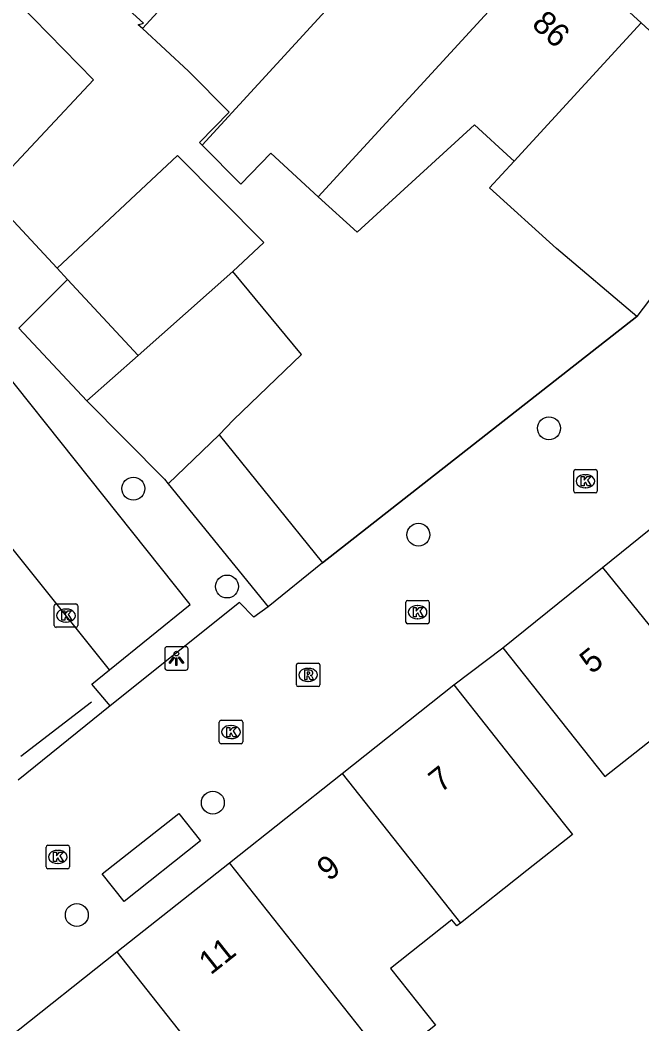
# Model space of a CAD drawing. Extents: x 161882 to 162509, y 381687 to 382379.
# Drawn here: x 162126.63 to 162153.19, y 382093.23 to 382136.14 of the extents above; entities that cross this region are included whole.
import ezdxf

# ---------------------------------------------------------------- set-up
doc = ezdxf.new("R2010")
doc.units = 0
for name, color, linetype in [('IMGEO_Boom', 7, 'Continuous'), ('IMGEO_Groenvoorziening', 7, 'Continuous'), ('IMGEO_Hek', 7, 'Continuous'), ('IMGEO_Kolk', 7, 'Continuous'), ('IMGEO_Lichtpunt', 7, 'Continuous'), ('IMGEO_Muur', 7, 'Continuous'), ('IMGEO_Pand', 7, 'Continuous'), ('IMGEO_Pand_nummerreeks', 7, 'Continuous'), ('IMGEO_Parkeervlak_open', 7, 'Continuous'), ('IMGEO_Rijbaan_lokaal_open', 7, 'Continuous'), ('IMGEO_Rioolput', 7, 'Continuous'), ('IMGEO_Woonerf_open', 7, 'Continuous')]:
    doc.layers.add(name, color=color, linetype=linetype)

msp = doc.modelspace()

# ---------------------------------------------------------------- linework, layer by layer
at = {"layer": 'IMGEO_Boom'}
for centre in [(162149.22, 382118.691), (162131.465, 382116.112), (162143.644, 382114.141), (162135.468, 382111.927), (162134.861, 382102.686), (162129.049, 382097.887)]:
    msp.add_circle(centre, 0.489, dxfattribs=at)
at = {"layer": 'IMGEO_Groenvoorziening'}
msp.add_lwpolyline([(162126.569, 382122.976), (162129.478, 382119.862)], dxfattribs=at)
at = {"layer": 'IMGEO_Hek'}
msp.add_lwpolyline([(162126.654, 382104.673), (162129.678, 382107.004)], dxfattribs=at)
at = {"layer": 'IMGEO_Kolk'}
for p, q in [((162150.355, 382116.928), (162151.207, 382116.928)), ((162150.28, 382116.002), (162150.28, 382116.854)), ((162150.768, 382116.708), (162150.793, 382116.708)), ((162151.281, 382116.854), (162151.281, 382116.002)), ((162150.791, 382116.148), (162150.766, 382116.148)), ((162151.207, 382115.928), (162150.355, 382115.928)), ((162128.087, 382110.257), (162128.087, 382111.109)), ((162128.162, 382111.183), (162129.014, 382111.183)), ((162128.575, 382110.963), (162128.6, 382110.963)), ((162129.088, 382111.109), (162129.088, 382110.257)), ((162143.108, 382110.406), (162143.108, 382111.258)), ((162143.183, 382111.332), (162144.035, 382111.332)), ((162143.596, 382111.112), (162143.621, 382111.112)), ((162144.109, 382111.258), (162144.109, 382110.406)), ((162143.619, 382110.552), (162143.594, 382110.552)), ((162129.014, 382110.183), (162128.162, 382110.183)), ((162128.598, 382110.403), (162128.573, 382110.403)), ((162144.035, 382110.332), (162143.183, 382110.332)), ((162135.212, 382106.208), (162136.064, 382106.208)), ((162135.137, 382105.282), (162135.137, 382106.134)), ((162135.625, 382105.988), (162135.65, 382105.988)), ((162136.138, 382106.134), (162136.138, 382105.282)), ((162135.648, 382105.428), (162135.623, 382105.428)), ((162136.064, 382105.208), (162135.212, 382105.208)), ((162127.737, 382099.941), (162127.737, 382100.793)), ((162127.812, 382100.867), (162128.664, 382100.867)), ((162128.225, 382100.647), (162128.25, 382100.647)), ((162128.738, 382100.793), (162128.738, 382099.941)), ((162128.664, 382099.867), (162127.812, 382099.867)), ((162128.248, 382100.087), (162128.223, 382100.087))]:
    msp.add_line(p, q, dxfattribs=at)
for points in [[(162150.355, 382116.928), (162151.207, 382116.928)], [(162150.28, 382116.002), (162150.28, 382116.854)], [(162150.601, 382116.628), (162150.724, 382116.628), (162150.724, 382116.477), (162150.854, 382116.628), (162151.018, 382116.628), (162150.872, 382116.477), (162151.025, 382116.228), (162150.873, 382116.228), (162150.788, 382116.392), (162150.724, 382116.325), (162150.724, 382116.228), (162150.601, 382116.228), (162150.601, 382116.628)], [(162151.281, 382116.854), (162151.281, 382116.002)], [(162151.207, 382115.928), (162150.355, 382115.928)], [(162128.087, 382110.257), (162128.087, 382111.109)], [(162128.162, 382111.183), (162129.014, 382111.183)], [(162129.088, 382111.109), (162129.088, 382110.257)], [(162143.108, 382110.406), (162143.108, 382111.258)], [(162143.183, 382111.332), (162144.035, 382111.332)], [(162143.429, 382111.032), (162143.552, 382111.032), (162143.552, 382110.881), (162143.682, 382111.032), (162143.846, 382111.032), (162143.7, 382110.881), (162143.853, 382110.632), (162143.701, 382110.632), (162143.616, 382110.796), (162143.552, 382110.729), (162143.552, 382110.632), (162143.429, 382110.632), (162143.429, 382111.032)], [(162144.109, 382111.258), (162144.109, 382110.406)], [(162128.408, 382110.883), (162128.531, 382110.883), (162128.531, 382110.732), (162128.661, 382110.883), (162128.825, 382110.883), (162128.679, 382110.732), (162128.832, 382110.483), (162128.68, 382110.483), (162128.595, 382110.647), (162128.531, 382110.58), (162128.531, 382110.483), (162128.408, 382110.483), (162128.408, 382110.883)], [(162129.014, 382110.183), (162128.162, 382110.183)], [(162144.035, 382110.332), (162143.183, 382110.332)], [(162135.212, 382106.208), (162136.064, 382106.208)], [(162135.137, 382105.282), (162135.137, 382106.134)], [(162135.458, 382105.908), (162135.581, 382105.908), (162135.581, 382105.757), (162135.711, 382105.908), (162135.875, 382105.908), (162135.729, 382105.757), (162135.882, 382105.508), (162135.73, 382105.508), (162135.645, 382105.672), (162135.581, 382105.605), (162135.581, 382105.508), (162135.458, 382105.508), (162135.458, 382105.908)], [(162136.138, 382106.134), (162136.138, 382105.282)], [(162136.064, 382105.208), (162135.212, 382105.208)], [(162127.737, 382099.941), (162127.737, 382100.793)], [(162127.812, 382100.867), (162128.664, 382100.867)], [(162128.738, 382100.793), (162128.738, 382099.941)], [(162128.058, 382100.567), (162128.181, 382100.567), (162128.181, 382100.416), (162128.311, 382100.567), (162128.475, 382100.567), (162128.329, 382100.416), (162128.482, 382100.167), (162128.33, 382100.167), (162128.245, 382100.331), (162128.181, 382100.264), (162128.181, 382100.167), (162128.058, 382100.167), (162128.058, 382100.567)], [(162128.664, 382099.867), (162127.812, 382099.867)]]:
    msp.add_lwpolyline(points, dxfattribs=at)
for centre, start, end in [((162150.357, 382116.852), 91.552, 178.448), ((162150.357, 382116.852), 91.552, 178.448), ((162151.205, 382116.852), 1.552, 88.448), ((162151.205, 382116.852), 1.552, 88.448), ((162150.357, 382116.004), 181.552, 268.448), ((162150.357, 382116.004), 181.552, 268.448), ((162151.205, 382116.004), 271.552, 358.448), ((162151.205, 382116.004), 271.552, 358.448), ((162128.164, 382111.107), 91.552, 178.448), ((162128.164, 382111.107), 91.552, 178.448), ((162129.012, 382111.107), 1.552, 88.448), ((162129.012, 382111.107), 1.552, 88.448), ((162143.185, 382111.256), 91.552, 178.448), ((162143.185, 382111.256), 91.552, 178.448), ((162144.033, 382111.256), 1.552, 88.448), ((162144.033, 382111.256), 1.552, 88.448), ((162128.164, 382110.259), 181.552, 268.448), ((162128.164, 382110.259), 181.552, 268.448), ((162129.012, 382110.259), 271.552, 358.448), ((162129.012, 382110.259), 271.552, 358.448), ((162143.185, 382110.408), 181.552, 268.448), ((162143.185, 382110.408), 181.552, 268.448), ((162144.033, 382110.408), 271.552, 358.448), ((162144.033, 382110.408), 271.552, 358.448), ((162135.214, 382106.132), 91.552, 178.448), ((162135.214, 382106.132), 91.552, 178.448), ((162136.062, 382106.132), 1.552, 88.448), ((162136.062, 382106.132), 1.552, 88.448), ((162135.214, 382105.284), 181.552, 268.448), ((162135.214, 382105.284), 181.552, 268.448), ((162136.062, 382105.284), 271.552, 358.448), ((162136.062, 382105.284), 271.552, 358.448), ((162127.814, 382100.791), 91.552, 178.448), ((162127.814, 382100.791), 91.552, 178.448), ((162128.662, 382100.791), 1.552, 88.448), ((162128.662, 382100.791), 1.552, 88.448), ((162127.814, 382099.943), 181.552, 268.448), ((162127.814, 382099.943), 181.552, 268.448), ((162128.662, 382099.943), 271.552, 358.448), ((162128.662, 382099.943), 271.552, 358.448)]:
    msp.add_arc(centre, 0.0765, start, end, dxfattribs=at)
for centre, major_axis, ratio, start_param, end_param in [((162150.767, 382116.428), (-0.387, 0.002), 0.722429, 4.712389, 7.853982), ((162150.792, 382116.428), (-0.39, 0.002), 0.717154, 1.570796, 4.712389), ((162128.574, 382110.683), (-0.387, 0.002), 0.722429, 4.712389, 7.853982), ((162128.599, 382110.683), (-0.39, 0.002), 0.717154, 1.570796, 4.712389), ((162143.595, 382110.832), (-0.387, 0.002), 0.722429, 4.712389, 7.853982), ((162143.62, 382110.832), (-0.39, 0.002), 0.717154, 1.570796, 4.712389), ((162135.624, 382105.708), (-0.387, 0.002), 0.722429, 4.712389, 7.853982), ((162135.649, 382105.708), (-0.39, 0.002), 0.717154, 1.570796, 4.712389), ((162128.224, 382100.367), (-0.387, 0.002), 0.722429, 4.712389, 7.853982), ((162128.249, 382100.367), (-0.39, 0.002), 0.717154, 1.570796, 4.712389)]:
    msp.add_ellipse(centre, major_axis=major_axis, ratio=ratio, start_param=start_param, end_param=end_param, dxfattribs=at)
at = {"layer": 'IMGEO_Lichtpunt'}
for p, q in [((162132.805, 382109.26), (162132.805, 382108.453)), ((162132.805, 382109.26), (162132.805, 382108.453)), ((162133.707, 382109.355), (162132.899, 382109.355)), ((162133.707, 382109.355), (162132.899, 382109.355)), ((162133.801, 382108.453), (162133.801, 382109.26)), ((162133.801, 382108.453), (162133.801, 382109.26)), ((162132.899, 382108.359), (162133.707, 382108.359)), ((162132.899, 382108.359), (162133.707, 382108.359))]:
    msp.add_line(p, q, dxfattribs=at)
for points in [[(162133.179, 382108.924), (162133.218, 382108.896), (162133.03, 382108.634), (162132.992, 382108.661), (162133.179, 382108.924)], [(162133.281, 382108.876), (162133.328, 382108.876), (162133.328, 382108.554), (162133.281, 382108.554), (162133.281, 382108.876)], [(162133.391, 382108.896), (162133.429, 382108.923), (162133.616, 382108.661), (162133.577, 382108.633), (162133.391, 382108.896)]]:
    msp.add_lwpolyline(points, dxfattribs=at)
msp.add_circle((162133.304, 382109.058), 0.0994, dxfattribs=at)
for centre, start, end in [((162132.899, 382109.26), 90, 180), ((162132.899, 382109.26), 90, 180), ((162133.707, 382109.26), 0, 90), ((162133.707, 382109.26), 0, 90), ((162132.899, 382108.453), 180, 270), ((162132.899, 382108.453), 180, 270), ((162133.707, 382108.453), 270, 0), ((162133.707, 382108.453), 270, 360)]:
    msp.add_arc(centre, 0.0946, start, end, dxfattribs=at)
at = {"layer": 'IMGEO_Muur'}
msp.add_lwpolyline([(162139.55, 382112.943), (162152.969, 382123.476)], dxfattribs=at)
at = {"layer": 'IMGEO_Pand'}
for points in [[(162131.849, 382135.773), (162131.669, 382135.938), (162131.894, 382136.009), (162129.716, 382138.006), (162133.943, 382142.615), (162132.309, 382144.112), (162134.424, 382146.419), (162137.803, 382150.104)], [(162141.709, 382146.522), (162131.849, 382135.773)], [(162134.405, 382130.798), (162145.576, 382142.975)], [(162149.37, 382139.496), (162139.366, 382128.589)], [(162149.37, 382139.496), (162153.156, 382136.024)], [(162120.058, 382131.359), (162125.918, 382137.539), (162129.757, 382133.588), (162125.219, 382128.746)], [(162147.733, 382130.112), (162153.156, 382136.024)], [(162153.156, 382136.024), (162157.689, 382131.867), (162158.024, 382129.831), (162157.745, 382129.743), (162155.369, 382126.625)], [(162131.849, 382135.773), (162133.827, 382133.959), (162135.557, 382132.207), (162134.295, 382130.91), (162134.405, 382130.798)], [(162139.366, 382128.589), (162141.02, 382127.073), (162146.041, 382131.663), (162147.597, 382130.236), (162147.733, 382130.112)], [(162139.366, 382128.589), (162137.342, 382130.446), (162136.056, 382129.125), (162134.405, 382130.798)], [(162135.718, 382125.396), (162137.042, 382126.634), (162133.354, 382130.351), (162128.203, 382125.536)], [(162152.969, 382123.476), (162149.536, 382126.372), (162146.684, 382128.969), (162147.733, 382130.112)], [(162128.203, 382125.536), (162125.219, 382128.746)], [(162155.369, 382126.625), (162152.969, 382123.476)], [(162128.203, 382125.536), (162128.651, 382125.054)], [(162131.67, 382121.806), (162135.718, 382125.396)], [(162135.128, 382118.408), (162135.749, 382119.057), (162138.653, 382121.846), (162135.718, 382125.396)], [(162128.651, 382125.054), (162126.569, 382122.976)], [(162131.67, 382121.806), (162128.651, 382125.054)], [(162129.478, 382119.862), (162131.67, 382121.806)], [(162129.478, 382119.862), (162132.796, 382116.521), (162132.956, 382116.323)], [(162132.956, 382116.323), (162135.128, 382118.408)], [(162135.128, 382118.408), (162139.55, 382112.943)], [(162132.956, 382116.323), (162137.218, 382111.056)], [(162151.509, 382112.743), (162155.061, 382115.61)], [(162139.55, 382112.943), (162137.218, 382111.056)], [(162147.247, 382109.304), (162151.509, 382112.743)], [(162151.509, 382112.743), (162155.548, 382107.736)], [(162147.247, 382109.304), (162150.352, 382105.385), (162151.606, 382103.803), (162153.966, 382105.673), (162155.951, 382103.169), (162157.952, 382104.755)], [(162140.384, 382103.935), (162145.159, 382107.718)], [(162145.159, 382107.718), (162148.264, 382103.799), (162150.222, 382101.329), (162148.282, 382099.792), (162145.441, 382097.542)], [(162135.571, 382100.121), (162140.384, 382103.935)], [(162140.384, 382103.935), (162145.441, 382097.542)], [(162130.756, 382096.306), (162135.571, 382100.121)], [(162142.34, 382091.565), (162135.571, 382100.121)], [(162145.441, 382097.542), (162145.285, 382097.418), (162145.072, 382097.687), (162142.444, 382095.605), (162144.371, 382093.174), (162142.34, 382091.565)], [(162126.131, 382092.642), (162130.756, 382096.306)], [(162130.756, 382096.306), (162135.52, 382090.284)]]:
    msp.add_lwpolyline(points, dxfattribs=at)
at = {"layer": 'IMGEO_Parkeervlak_open'}
msp.add_lwpolyline([(162130.444, 382108.362), (162133.886, 382111.152), (162120.906, 382127.458), (162117.385, 382124.671)], dxfattribs=at)
at = {"layer": 'IMGEO_Rijbaan_lokaal_open'}
for points in [[(162130.444, 382108.362), (162117.385, 382124.671)], [(162130.473, 382106.822), (162129.686, 382107.748), (162130.444, 382108.362)], [(162130.473, 382106.822), (162126.539, 382103.647)]]:
    msp.add_lwpolyline(points, dxfattribs=at)
at = {"layer": 'IMGEO_Rioolput'}
for p, q in [((162138.433, 382107.722), (162138.433, 382108.574)), ((162138.508, 382108.648), (162139.36, 382108.648)), ((162138.921, 382108.428), (162138.946, 382108.428)), ((162139.434, 382108.574), (162139.434, 382107.722)), ((162139.36, 382107.648), (162138.508, 382107.648)), ((162138.944, 382107.868), (162138.919, 382107.868))]:
    msp.add_line(p, q, dxfattribs=at)
for points in [[(162138.433, 382107.722), (162138.433, 382108.574)], [(162138.508, 382108.648), (162139.36, 382108.648)], [(162139.022, 382108.346), (162138.77, 382108.348), (162138.77, 382107.948)], [(162139.434, 382108.574), (162139.434, 382107.722)], [(162138.77, 382107.948), (162138.894, 382107.948), (162138.894, 382108.11), (162138.905, 382108.11)], [(162138.948, 382108.267), (162138.894, 382108.267), (162138.894, 382108.186)], [(162138.894, 382108.186), (162138.946, 382108.186)], [(162138.952, 382108.081), (162139.023, 382107.948), (162139.163, 382107.948), (162139.098, 382108.074)], [(162139.36, 382107.648), (162138.508, 382107.648)]]:
    msp.add_lwpolyline(points, dxfattribs=at)
for centre, radius, start, end in [((162138.51, 382108.572), 0.0765, 91.552, 178.448), ((162138.51, 382108.572), 0.0765, 91.552, 178.448), ((162139.021, 382108.236), 0.109, 350.3612, 89.416), ((162139.358, 382108.572), 0.0765, 1.552, 88.448), ((162139.358, 382108.572), 0.0765, 1.552, 88.448), ((162138.904, 382108.057), 0.0533, 26.0293, 88.6989), ((162138.93, 382108.375), 0.19, 274.7715, 282.9687), ((162138.954, 382108.171), 0.0964, 77.0061, 93.1865), ((162138.968, 382108.228), 0.0378, 276.6634, 79.6772), ((162139.019, 382108.236), 0.112, 277.5842, 350.9817), ((162139.003, 382108.021), 0.108, 29.5134, 73.7905), ((162138.51, 382107.724), 0.0765, 181.552, 268.448), ((162138.51, 382107.724), 0.0765, 181.552, 268.448), ((162139.358, 382107.724), 0.0765, 271.552, 358.448), ((162139.358, 382107.724), 0.0765, 271.552, 358.448)]:
    msp.add_arc(centre, radius, start, end, dxfattribs=at)
for centre, major_axis, ratio, start_param, end_param in [((162138.92, 382108.148), (-0.387, 0.002), 0.722429, 4.712389, 7.853982), ((162138.945, 382108.148), (-0.39, 0.002), 0.717154, 1.570796, 4.712389)]:
    msp.add_ellipse(centre, major_axis=major_axis, ratio=ratio, start_param=start_param, end_param=end_param, dxfattribs=at)
at = {"layer": 'IMGEO_Woonerf_open'}
for points in [[(162152.969, 382123.476), (162139.55, 382112.943)], [(162137.218, 382111.056), (162136.61, 382110.616), (162136.002, 382111.248), (162130.473, 382106.822)], [(162145.159, 382107.718), (162147.247, 382109.304)], [(162130.136, 382099.641), (162133.403, 382102.23), (162134.337, 382101.051), (162131.069, 382098.463), (162130.136, 382099.641)]]:
    msp.add_lwpolyline(points, dxfattribs=at)

# ---------------------------------------------------------------- texts
at = {"layer": 'IMGEO_Pand_nummerreeks'}
for s, rotation, p in [('86', 317.4751, (162148.438, 382135.902)), ('5', 38.9038, (162151.047, 382108.156)), ('7', 38.3882, (162144.591, 382103.083)), ('9', 38.39, (162139.814, 382099.298)), ('11', 38.39, (162134.766, 382095.298))]:
    msp.add_text(s, height=1, rotation=rotation, dxfattribs=at).set_placement(p)

doc.saveas('drawing.dxf')
